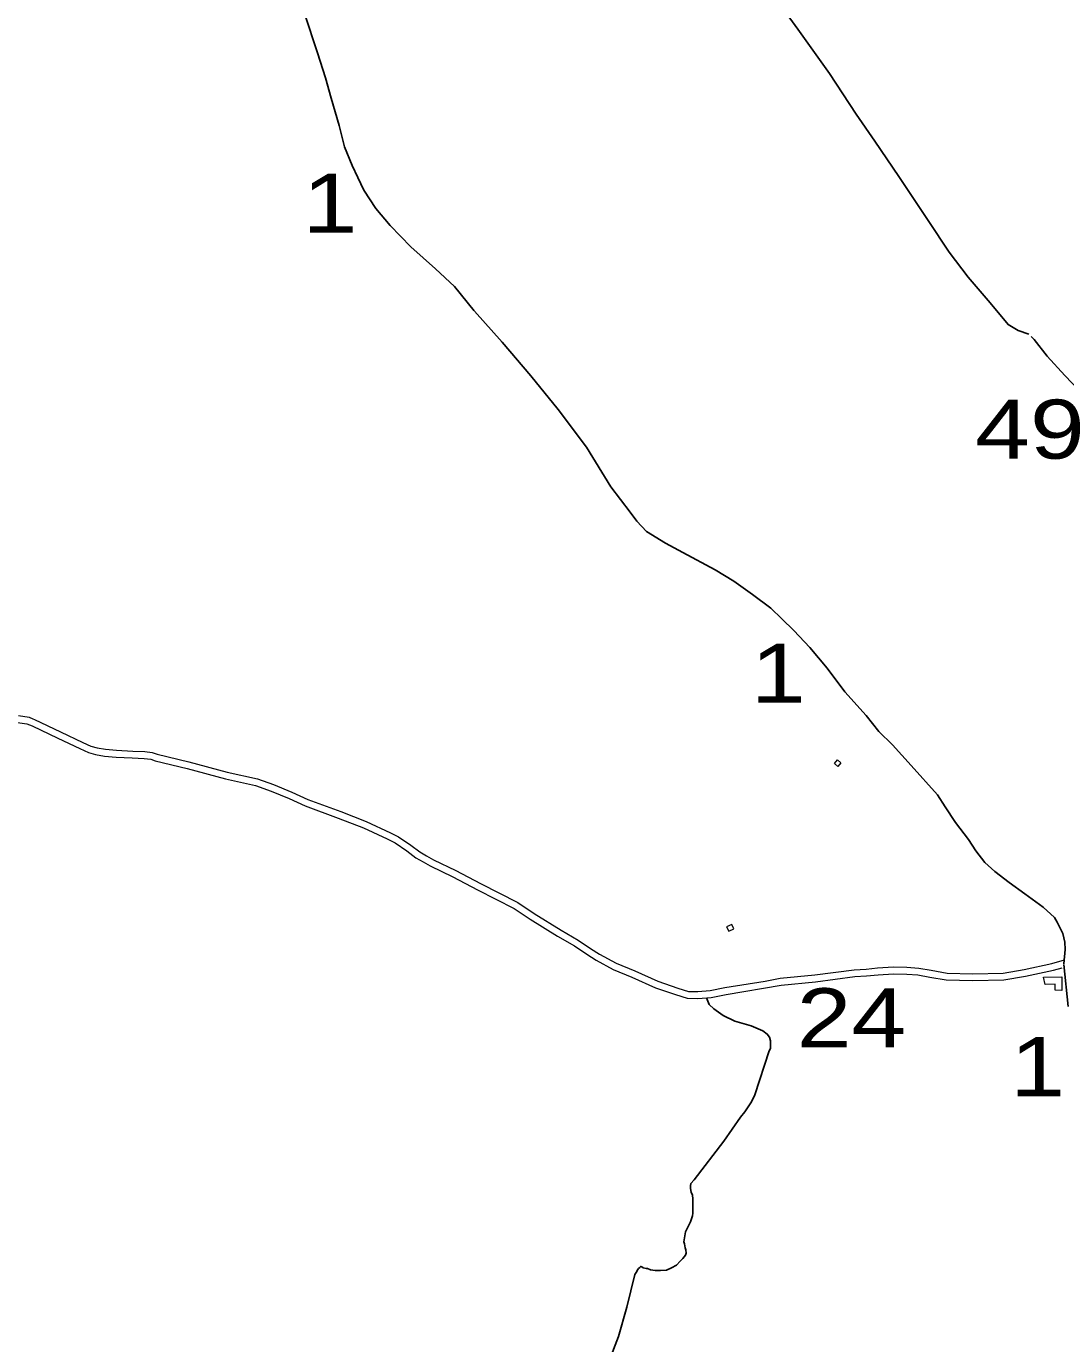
# Model space of a CAD drawing. Extents: x 476989 to 498418, y 4381813 to 4416555.
# Drawn here: x 485532 to 486413, y 4387137 to 4388253 of the extents above; entities that cross this region are included whole.
import ezdxf
from ezdxf.enums import TextEntityAlignment as Align

# ---------------------------------------------------------------- set-up
doc = ezdxf.new("R2010")
doc.units = 0
doc.header["$LTSCALE"] = 20
doc.linetypes.add('MEDIUM_DASHED', pattern=[4.5, 3, -1.5])
for name, color, linetype, lineweight in [('13', 7, 'Continuous', 13), ('36', 7, 'Continuous', 13), ('47', 7, 'Continuous', 13), ('48', 7, 'MEDIUM_DASHED', 13), ('6', 7, 'Continuous', 25)]:
    doc.layers.add(name, color=color, linetype=linetype, lineweight=lineweight)

msp = doc.modelspace()

# ---------------------------------------------------------------- linework, layer by layer
at = {"layer": '36'}
for points in [[(485525.85, 4387669.03), (485534.71, 4387667.62), (485537.94, 4387666.38), (485539.28, 4387665.58), (485561.41, 4387655.37), (485580.28, 4387646.32), (485586.96, 4387643.16), (485592.33, 4387641.73), (485599.42, 4387640.44), (485608.78, 4387639.71), (485622.5, 4387638.98), (485632.69, 4387638.46), (485639.02, 4387637.77), (485643.14, 4387636.43), (485670.12, 4387629.89), (485702.71, 4387621.09), (485728.3, 4387615.4), (485741.97, 4387610.63), (485757.5, 4387604.24), (485770.99, 4387598.04), (485798.82, 4387587.68), (485820.32, 4387579.33), (485840.91, 4387569.8), (485847.92, 4387566.17), (485858.19, 4387559.27), (485865.91, 4387553.53), (485871.63, 4387550.07), (485877.42, 4387546.92), (485896.42, 4387537.64), (485917.43, 4387526.69), (485948.87, 4387510.62), (485962.71, 4387501.42), (485985.53, 4387487.21), (485999.97, 4387478.82), (486010.53, 4387471.69), (486018.26, 4387466.93), (486032.24, 4387459.24), (486047.97, 4387452.71), (486067.73, 4387443.96), (486084.52, 4387438.16), (486093.46, 4387435.34), (486101.37, 4387435.15), (486111.95, 4387436.05), (486124.36, 4387438.5), (486158.65, 4387443.94), (486171.22, 4387446.53), (486200.61, 4387449.41), (486233.99, 4387453.74), (486244.06, 4387454.27), (486253.83, 4387455.33), (486267.28, 4387456.04), (486278.77, 4387455.87), (486288.75, 4387455.13), (486299.24, 4387453.26), (486312.7, 4387450.89), (486334.51, 4387450.35), (486360.31, 4387450.88), (486377.98, 4387454), (486401.45, 4387458.91), (486412.26, 4387462.09)], [(485524.84, 4387663.24), (485532.77, 4387661.98), (485537.4, 4387660.22), (485559.04, 4387649.99), (485577.75, 4387641.02), (485584.93, 4387637.62), (485591.05, 4387636), (485598.66, 4387634.6), (485608.4, 4387633.84), (485622.19, 4387633.11), (485632.22, 4387632.6), (485637.78, 4387631.99), (485641.54, 4387630.77), (485668.67, 4387624.2), (485701.31, 4387615.39), (485726.69, 4387609.74), (485739.89, 4387605.13), (485755.16, 4387598.85), (485768.73, 4387592.61), (485796.73, 4387582.18), (485818.02, 4387573.92), (485838.32, 4387564.52), (485844.92, 4387561.11), (485854.8, 4387554.47), (485862.63, 4387548.64), (485868.7, 4387544.98), (485874.73, 4387541.7), (485893.77, 4387532.39), (485914.74, 4387521.47), (485945.9, 4387505.54), (485959.53, 4387496.48), (485982.5, 4387482.18), (485996.85, 4387473.84), (486007.34, 4387466.75), (486015.3, 4387461.85), (486029.69, 4387453.94), (486045.65, 4387447.31), (486065.57, 4387438.48), (486082.67, 4387432.58), (486092.49, 4387429.48), (486101.55, 4387429.27), (486112.77, 4387430.22), (486125.48, 4387432.73), (486172.11, 4387440.71), (486201.27, 4387443.57), (486234.53, 4387447.88), (486244.53, 4387448.41), (486254.3, 4387449.47), (486267.39, 4387450.16), (486278.51, 4387450), (486288.02, 4387449.29), (486298.22, 4387447.47), (486312.11, 4387445.02), (486334.5, 4387444.47), (486360.89, 4387445.01), (486379.09, 4387448.22), (486402.88, 4387453.21), (486410.26, 4387455.38)]]:
    msp.add_lwpolyline(points, dxfattribs=at)
at = {"layer": '47'}
msp.add_lwpolyline([(486394.5, 4387447.43), (486409.96, 4387447.66), (486410.13, 4387436.18), (486404.24, 4387436.34), (486404.37, 4387441.42), (486395.98, 4387441.26)], close=True, dxfattribs=at)
at = {"layer": '48'}
for points in [[(486222.79, 4387629), (486220.04, 4387625.87), (486217.23, 4387628.33), (486219.98, 4387631.46)], [(486125.88, 4387490.15), (486127.64, 4387486.28), (486132, 4387488.26), (486130.24, 4387492.13)]]:
    msp.add_lwpolyline(points, close=True, dxfattribs=at)
at = {"layer": '6'}
for points in [[(486169.13, 4388274.35), (486186.31, 4388250.53), (486213.19, 4388213.09), (486235.61, 4388178.6), (486251.45, 4388155.76), (486271.85, 4388125.77), (486296.82, 4388088.37), (486314.6, 4388061.76), (486330.73, 4388040.49), (486349.4, 4388018.73), (486364.43, 4388000.31), (486372.86, 4387995.35), (486382.16, 4387992.25)], [(485768, 4388263.85), (485779.02, 4388230.66), (485785.91, 4388209.4), (485790.76, 4388192.02), (485797.49, 4388169.1), (485801.96, 4388151.04), (485808.65, 4388135.09), (485813.43, 4388124.82), (485818.42, 4388114.08), (485828.47, 4388098.7), (485840.76, 4388084.25), (485858.12, 4388066.2), (485879.3, 4388047.48), (485895.16, 4388032.58), (485911.89, 4388012.02)], [(485912.17, 4388011.78), (485935.61, 4387985.33), (485960.06, 4387956.84), (485983.16, 4387928.35), (486007.28, 4387896.47), (486027.88, 4387862.88), (486044.27, 4387841.38), (486049.75, 4387833.89), (486058.02, 4387825.05), (486074.09, 4387815.1), (486088.73, 4387807.17), (486116.23, 4387792.4)], [(486383.88, 4387990.09), (486386.63, 4387987.64), (486397.48, 4387973.58), (486412.62, 4387957.15), (486430.7, 4387938.38), (486461.98, 4387901.19), (486486.91, 4387869.73), (486502.64, 4387845.57), (486522.26, 4387819.72), (486543.26, 4387788.72)], [(486116.23, 4387792.4), (486132.03, 4387782.95), (486147.96, 4387771.75), (486163.27, 4387760.17), (486172.57, 4387751.14), (486183, 4387741), (486196.38, 4387726.7), (486211.2, 4387709.12), (486226.06, 4387689.1), (486244.26, 4387669.22), (486254.87, 4387655.62), (486266.52, 4387644.16), (486282.31, 4387626.78), (486304.74, 4387601.82), (486311.03, 4387591.7), (486319.95, 4387578.44), (486330.78, 4387563.95), (486337.26, 4387554.38), (486344.84, 4387544.52), (486353.11, 4387536.82), (486365.48, 4387527.49), (486378.58, 4387517.9), (486394.08, 4387506.62), (486403.68, 4387498.03), (486406.02, 4387494.04)], [(486406.02, 4387494.04), (486410.83, 4387484.53), (486412.59, 4387477.02), (486412.95, 4387470.73), (486411.61, 4387458.73)], [(486411.61, 4387458.24), (486415.3, 4387422.43)], [(486108.72, 4387429.88), (486111.15, 4387424.2), (486115.09, 4387420.58), (486123.07, 4387414.99), (486132.97, 4387410.05), (486146.69, 4387406.04), (486156.54, 4387401.92), (486160.35, 4387399.14), (486162.24, 4387396.44), (486163.03, 4387393.52), (486163.22, 4387390.05), (486163.01, 4387387.04), (486162.1, 4387384.84), (486149.71, 4387347.62), (486147.02, 4387341.86), (486144.83, 4387338.28), (486141.42, 4387333.4), (486137.75, 4387328.8), (486123.51, 4387308.31), (486098.49, 4387275.55)], [(486098.49, 4387275.55), (486095.45, 4387272.46), (486095.42, 4387270.58), (486095.4, 4387269.3), (486095.39, 4387268.63), (486095.81, 4387264.82)], [(486019.79, 4387105.48), (486034.18, 4387142.83), (486041.39, 4387167.75), (486048.03, 4387195.58), (486049.73, 4387197.92), (486050.22, 4387198.85), (486051.3, 4387200.5), (486052.27, 4387201.5), (486053.26, 4387202.33), (486053.18, 4387202.28), (486052.94, 4387202.28), (486054.06, 4387201.94), (486055.28, 4387201.23), (486057.62, 4387200.6), (486058.76, 4387200.43), (486061.5, 4387199.5), (486065.29, 4387198.87), (486069.79, 4387198.81), (486074.96, 4387199.22), (486079.22, 4387201.03), (486083.33, 4387203.26), (486086.51, 4387206.74), (486088.66, 4387209.06), (486090.93, 4387211.75), (486091.67, 4387213.64), (486091.33, 4387216.29), (486090.88, 4387218.02), (486090.18, 4387221.36), (486089.63, 4387223.21), (486091.15, 4387231.55), (486095.34, 4387240.23), (486097, 4387245.29), (486097.29, 4387247.57), (486097.32, 4387249.61), (486097.36, 4387252.18), (486097.33, 4387255.71), (486097.39, 4387259.56), (486097, 4387262.75), (486096.29, 4387264.23), (486095.81, 4387264.86)]]:
    msp.add_lwpolyline(points, dxfattribs=at)

# ---------------------------------------------------------------- texts
at = {"layer": '13', "width": 1.25}
msp.add_text('24', height=50, dxfattribs=at).set_placement((486231.73, 4387387.95), align=Align.CENTER)
at = {"layer": '6', "width": 1.25}
for s, p in [('1', (485789.69, 4388078.22)), ('49', (486382.99, 4387886.71)), ('1', (486169.71, 4387679.88)), ('1', (486389.45, 4387346.57))]:
    msp.add_text(s, height=50, dxfattribs=at).set_placement(p, align=Align.CENTER)

doc.saveas('drawing.dxf')
